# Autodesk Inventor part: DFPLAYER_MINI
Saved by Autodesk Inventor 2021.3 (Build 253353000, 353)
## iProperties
Created: 2021-12
Part Number: DFPLAYER_MINI
Material: Generic
Document SubType Name: Modeling
Designer: Administrator
Density: 1 g/cm^3
Appearance: Default
Title: DFPLAYER_MINI
Author: Administrator
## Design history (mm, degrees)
feature "Body1"
body "Solid1"
